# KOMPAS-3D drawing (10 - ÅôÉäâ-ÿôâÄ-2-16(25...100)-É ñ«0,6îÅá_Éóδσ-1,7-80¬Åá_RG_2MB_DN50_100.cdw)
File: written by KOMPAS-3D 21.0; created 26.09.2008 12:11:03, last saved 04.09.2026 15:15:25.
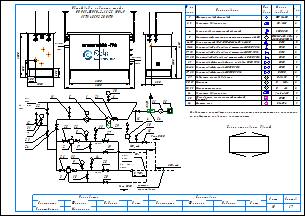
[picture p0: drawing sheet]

Sheets 1-2: A3, landscape

Document properties: Наименование: Макро:21; Автор: RaskoAdmin; Форматы листов документа: 2xA3; Полное имя файла: \\ur38nt01\Departments\КТО\КБ ПУРДГ\Заявки\Прайс-лист на типовые шкафы ГРПШ\ПУРДГ_стандарт_30_04_2026\ПУРДГ с RG_2MB\ПУРДГ-ШУГО-2-16(25...100)-Р до0,6МПа_Рвых-1,7-80кПа_RG_2MB_DN50_100.cdw

Title block, sheet 1: Наименование: Пункт учета газа / ПУГ-Ш-400-Р / ЛГТИ.485922.001ТУ; designation: ЛГТИ.03.4411141; sheet number: 1; Количество листов документа: 2; organisation: ООО "ЭЛЬСТЕР Газэлектроника"; Форматы листов документа: A3; stored path: C:\Рабочие документы\Компас\ПУГ\Схема.cdw; Разработал: Устинов; Проверил: Кошкин; Утвердил: Кошкин
Title block, sheet 2: sheet number: 2; stored path: D:\Рабочие документы\Заявки\ПУРДГ\ПУРДГ-ШУЭО-2-100-Р 4411220.cdw; designation, second copy: ЛГТИ.03.4411141-

Views: Вид 1, Вид 2
Referenced files: wcvoit.frw
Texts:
  Normal
  Общий вид и габариты шкафа
  ПУРДГ-ШУГО-2-16(25...100)-Р
  DN100
  Выход газа
  DN50
  Вход газа
  logo-rasko-ge.png
  DN 1
  местное
  сопротивление
  Римп DN20
  Выход
  газа
  Р=     кПа
  Вход
  Р=       МПа
  PDI
  № на
  схеме
  Усл.
  обозн.
  Марка
  (модель)
  Кол.
  Фильтр газовый фланцевый
  ФГ 16-50
  Регулятор давления газа
  RG/2MB
  Клапан предохранительный сбросной
  КПС DN20
  Измерительный комплекс с ротационным счетчиком Ду50
  СГ-ЭК-Р-(0,2...2,0)-
  Кран кнопочный VE-РАСКО-НЗ-1,6-G1/2-М20
  DN15
  Кран шаровой "под приварку" штуцерный DN20 PN16
  DN20
  Кран шаровой "под приварку" штуцерный DN15 PN16
  Кран шаровой "под приварку" штуцерный п/п DN20 PN16
  Кран шаровой фланцевый с мех. приводом DN50 PN16
  Кран шаровой фланцевый DN50 PN16
  Кран шаровой фланцевый DN100 PN16
  Индикатор перепада давления
  Манометр
  Манометр-напоромер
  Обогреватель газогорелочный шкафной
  (Эльтон")
  Счетчик газа
  Delta 15
  0...     МПа
  0...     кПа
  Venio-A-15
  ОГШН
  BK-G1,6
  Схема открывания дверей
  Предприятие изготовитель может заменять комплектующие на аналогичные,
  не ухудшающие заявленных характеристик.
  Должность
  Конструктор
  Фамилия
  Подпись
  Дата
  Согласовано
  Максимкин
  Лист
  Листов
  POLYLINE_STYLE_0.18_RGB_0_0_0
  POLYLINE_STYLE_0.50_RGB_0_0_0
  POLYLINE_STYLE_0.34_RGB_0_0_0
  PHANTOM_RGB_0_0_0_SC_1_THICK_0.18
  K5LT_THIN_RGB_0_0_0_THICK_0.18
  K5LT32769_RGB_0_0_0_THICK_0.18
  K5LT12_RGB_0_0_0_SC_1_THICK_0.18
  K5LT_DASHED_RGB_0_0_0_SC_1_THICK_0.18
  ACISOTGL_RGB_0_0_0_SC_0.8_THICK_0.25
  CONTINUOUS_RGB_0_127_31_THICK_0.3
  CONTINUOUS_RGB_0_0_255_THICK_0.35
  CONTINUOUS_RGB_255_0_0_THICK_0.35
  POLYLINE_STYLE_0.25_RGB_0_0_0
  CONTINUOUS_RGB_0_0_0_THICK_0.5
  POLYLINE_STYLE_0.35_RGB_0_0_255
  CONTINUOUS_RGB_0_0_0_THICK_0.4
  CONTINUOUS_RGB_0_0_0_THICK_0.35
  НЕВИДИМАЯ_RGB_0_0_0_SC_0.3_THICK_0.25
  СONTINUOUS_RGB_0_0_0_THICK_0.25
  ОСЕВАЯ2_RGB_248_153_30_SC_0.3_THICK_0.25
  Без оформления
Dimensions and other numbers on the sheet: 1; 1500; 250; 300; 1050; 550; 305; 2300; 4130; 2000; 2600; 5,,,7DN 1; 7; 31; 12; 22; 23; 24; 11; 5; 21; 6; 30; 25; 32; 8; 2; 17; 13; 27; 19; 4; 10; 15; 26; 33; 9; 3; 18; 14; 28; 20; 29; 2, 3; 6-10; 11-16; 17, 18; 19, 20; 22-26; 27, 28; 30, 31; 32, 33; 34; 35; 36; 16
